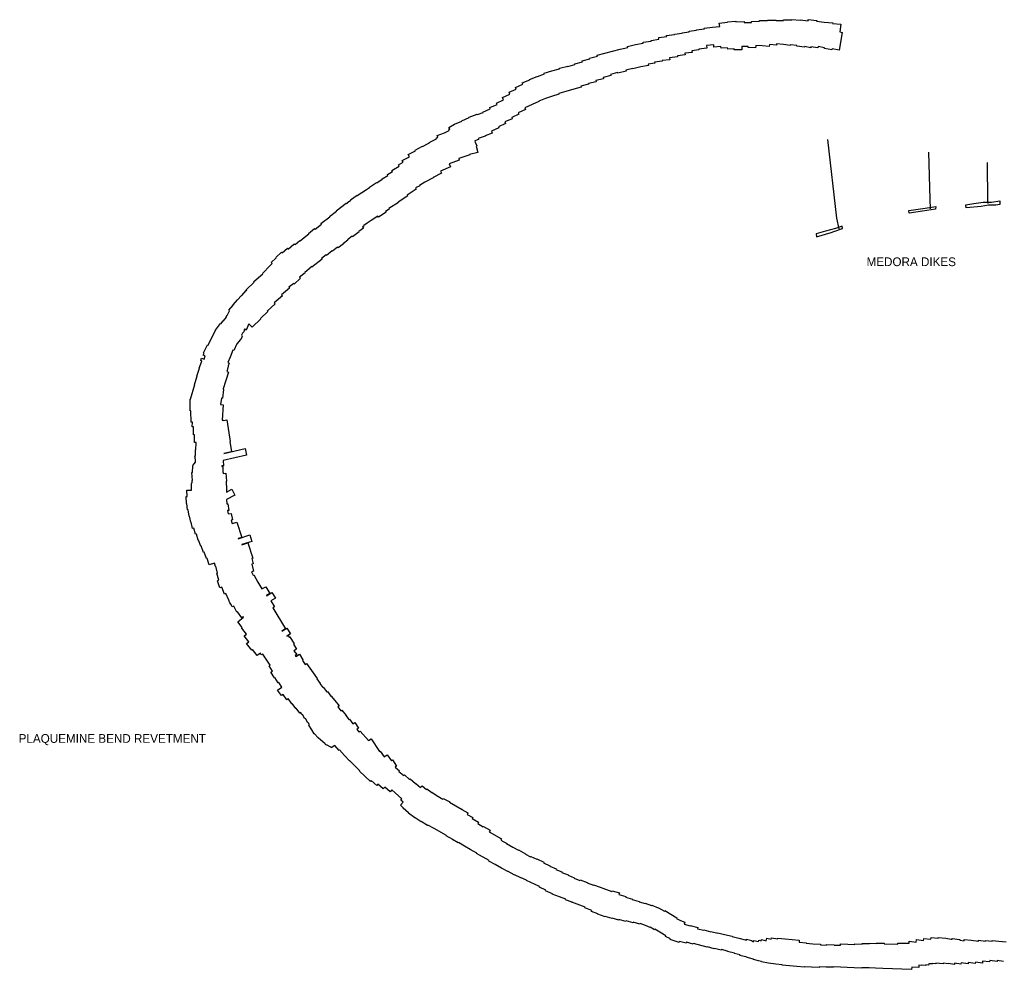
# Model space of a CAD drawing. Extents: x 2650582 to 3923188, y 277893 to 989177.
# Drawn here: x 3308830 to 3326824, y 645331 to 662763 of the extents above; entities that cross this region are included whole.
import ezdxf

# ---------------------------------------------------------------- set-up
doc = ezdxf.new("R2010")
doc.units = 0
doc.layers.add('Level 3', color=7, linetype='Continuous')

msp = doc.modelspace()

# ---------------------------------------------------------------- linework, layer by layer
at = {"layer": 'Level 3'}
for points in [[(3321674, 662633), (3321666, 662698), (3321815, 662714), (3321815, 662722), (3321968, 662731), (3321969, 662723), (3322123, 662725), (3322123, 662710), (3322259, 662710), (3322259, 662730), (3322406, 662731), (3322406, 662748)], [(3322406, 662748), (3322552, 662748), (3322552, 662751), (3322708, 662752), (3322708, 662748), (3322845, 662749), (3322845, 662759), (3322997, 662757), (3322997, 662763), (3323149, 662755), (3323149, 662757), (3323295, 662742), (3323297, 662762), (3323453, 662746), (3323452, 662732), (3323591, 662716), (3323591, 662718), (3323747, 662702), (3323746, 662694), (3323894, 662678), (3323879, 662536)], [(3320272, 662332), (3320270, 662347), (3320417, 662369), (3320416, 662380), (3320560, 662401), (3320556, 662434), (3320701, 662450), (3320698, 662470), (3320845, 662487), (3320843, 662497), (3320987, 662515), (3320986, 662522), (3321114, 662537), (3321113, 662553), (3321246, 662567), (3321246, 662574), (3321393, 662591), (3321391, 662604), (3321539, 662623), (3321674, 662633)], [(3323879, 662536), (3323921, 662528), (3323863, 662201), (3323735, 662224), (3323732, 662206), (3323594, 662230), (3323597, 662246), (3323478, 662267), (3323474, 662242), (3323346, 662265), (3323343, 662246), (3323228, 662266), (3323227, 662258), (3323088, 662275), (3323089, 662286), (3322970, 662300), (3322969, 662290), (3322845, 662305), (3322845, 662304), (3322716, 662316), (3322714, 662295), (3322585, 662306), (3322581, 662270), (3322452, 662281), (3322452, 662280), (3322335, 662290), (3322333, 662246), (3322194, 662251), (3322194, 662266), (3322082, 662266), (3322082, 662206), (3321942, 662206), (3321942, 662227), (3321821, 662222), (3321820, 662245), (3321699, 662236), (3321697, 662266), (3321567, 662257), (3321564, 662302)], [(3317589, 661206), (3317578, 661232), (3317710, 661289), (3317690, 661335), (3317824, 661395), (3317809, 661428), (3317941, 661487), (3317928, 661518), (3318061, 661576), (3318050, 661602), (3318189, 661660), (3318186, 661666), (3318328, 661720), (3318329, 661718), (3318459, 661769), (3318455, 661780), (3318594, 661823), (3318594, 661821), (3318735, 661862), (3318733, 661869), (3318885, 661909), (3318886, 661904), (3319016, 661939), (3319014, 661952), (3319156, 661988), (3319151, 662007), (3319289, 662042), (3319287, 662052), (3319432, 662089), (3319427, 662107), (3319566, 662145), (3319566, 662145), (3319849, 662217), (3319849, 662220), (3319988, 662253), (3319985, 662270), (3320127, 662303), (3320272, 662332)], [(3321564, 662302), (3321433, 662286), (3321439, 662238), (3321291, 662221), (3321293, 662205), (3321163, 662190), (3321167, 662160), (3321036, 662145), (3321040, 662115), (3320897, 662097), (3320899, 662080), (3320753, 662063), (3320757, 662025), (3320618, 662010), (3320620, 662001), (3320479, 661981), (3320482, 661964), (3320359, 661946)], [(3320359, 661946), (3320365, 661920), (3320226, 661893), (3320081, 661859), (3320080, 661865), (3319953, 661835), (3319957, 661818), (3319803, 661780), (3319801, 661790), (3319673, 661757), (3319678, 661738), (3319537, 661700), (3319543, 661678), (3319400, 661642), (3319405, 661623), (3319264, 661589), (3319266, 661580), (3319125, 661544), (3319130, 661523), (3318997, 661487), (3318998, 661485), (3318852, 661446), (3318722, 661408), (3318725, 661396), (3318587, 661353), (3318586, 661354), (3318479, 661312), (3318479, 661313), (3318354, 661265), (3318357, 661258), (3318233, 661206), (3318234, 661203), (3318097, 661143), (3318111, 661113), (3317978, 661053), (3317991, 661024), (3317858, 660964), (3317868, 660941), (3317734, 660884), (3317747, 660856)], [(3316810, 660841), (3316809, 660844), (3316943, 660901), (3316941, 660905), (3317080, 660963), (3317078, 660969), (3317226, 661025), (3317228, 661020), (3317333, 661058), (3317330, 661065), (3317464, 661124), (3317454, 661147), (3317589, 661206)], [(3315851, 660179), (3315982, 660246), (3315961, 660286), (3316091, 660354), (3316084, 660366), (3316221, 660437), (3316222, 660436), (3316324, 660488), (3316324, 660489), (3316348, 660501), (3316346, 660506), (3316478, 660575), (3316470, 660589), (3316504, 660606), (3316493, 660637), (3316623, 660682), (3316708, 660726), (3316702, 660742), (3316722, 660749), (3316703, 660785), (3316810, 660841)], [(3317747, 660856), (3317614, 660797), (3317624, 660774), (3317489, 660714), (3317502, 660679), (3317372, 660632), (3317374, 660626), (3317244, 660578), (3317250, 660565), (3317180, 660536)], [(3323863, 658925), (3323820, 659119), (3323655, 660565)], [(3317180, 660536), (3317185, 660515), (3317220, 660447), (3317205, 660439), (3317235, 660325)], [(3317235, 660325), (3317086, 660286), (3317088, 660281), (3316885, 660211), (3316894, 660182), (3316708, 660118), (3316734, 660058), (3316551, 659978), (3316570, 659943), (3316417, 659864), (3316420, 659859), (3316265, 659782), (3316267, 659779), (3316169, 659719), (3316173, 659710), (3316104, 659679), (3316093, 659672), (3316107, 659650), (3315941, 659542), (3315951, 659527), (3315774, 659415), (3315781, 659403), (3315601, 659296), (3315610, 659282), (3315544, 659243), (3315554, 659227), (3315412, 659139), (3315400, 659158), (3315298, 659087), (3315296, 659089), (3315294, 659087)], [(3325543, 659291), (3325534, 659470), (3325510, 660330)], [(3314646, 659244), (3314640, 659253), (3314822, 659392), (3314826, 659387), (3314846, 659401), (3314843, 659405), (3314906, 659446), (3314900, 659456), (3315021, 659538), (3315022, 659537), (3315191, 659646), (3315192, 659644), (3315251, 659680), (3315248, 659685), (3315380, 659770), (3315382, 659768), (3315483, 659837), (3315481, 659841), (3315588, 659902), (3315578, 659919), (3315669, 659972), (3315658, 659992), (3315691, 660010), (3315690, 660010), (3315794, 660070), (3315781, 660096), (3315868, 660144), (3315851, 660179)], [(3326583, 660137), (3326589, 659426), (3326591, 659388)], [(3325153, 659212), (3325143, 659261), (3325441, 659301), (3325639, 659334)], [(3325639, 659334), (3325635, 659282), (3325394, 659247), (3325153, 659212)], [(3326198, 659309), (3326191, 659364), (3326334, 659385), (3326507, 659412), (3326658, 659413), (3326812, 659439)], [(3326812, 659439), (3326816, 659372), (3326738, 659359), (3326606, 659356), (3326473, 659334), (3326198, 659309)], [(3312990, 657788), (3312997, 657796), (3312988, 657806), (3313136, 657943), (3313125, 657958), (3313292, 658096), (3313287, 658100), (3313426, 658250), (3313463, 658289), (3313447, 658306), (3313539, 658391), (3313531, 658399), (3313633, 658495), (3313646, 658482), (3313745, 658570), (3313759, 658555), (3313761, 658556), (3313858, 658644), (3313865, 658637), (3313875, 658645), (3313884, 658633), (3313970, 658710), (3313976, 658703), (3314016, 658733), (3314022, 658738), (3314020, 658741), (3314135, 658833), (3314130, 658839), (3314241, 658930), (3314252, 658917), (3314366, 659008), (3314357, 659021), (3314521, 659144), (3314516, 659151), (3314646, 659244)], [(3315294, 659087), (3315295, 659086), (3315206, 659026), (3315207, 659025), (3315147, 658981), (3315149, 658979), (3315121, 658959), (3315140, 658934), (3315055, 658872), (3315059, 658867), (3314940, 658775), (3314931, 658786), (3314847, 658723), (3314852, 658717), (3314769, 658652), (3314773, 658647), (3314672, 658573), (3314662, 658587), (3314569, 658515), (3314564, 658521), (3314460, 658436), (3314452, 658445), (3314370, 658379), (3314381, 658364), (3314193, 658219), (3314183, 658232), (3314172, 658224), (3314177, 658218), (3314062, 658122), (3314067, 658117), (3313967, 658035), (3313984, 658016), (3313869, 657910), (3313860, 657920), (3313772, 657849), (3313784, 657834), (3313636, 657711), (3313652, 657692), (3313500, 657567), (3313518, 657546), (3313372, 657412), (3313382, 657403), (3313247, 657276), (3313253, 657269), (3313097, 657117), (3313035, 657180)], [(3323918, 658972), (3323801, 658930), (3323617, 658879), (3323445, 658828), (3323450, 658776)], [(3323450, 658776), (3323717, 658855), (3323769, 658872), (3323928, 658928), (3323918, 658972)], [(3312623, 657302), (3312619, 657306), (3312640, 657331), (3312638, 657332), (3312678, 657419), (3312668, 657428), (3312748, 657524), (3312745, 657527), (3312825, 657622), (3312829, 657618), (3312899, 657702), (3312905, 657697), (3312985, 657792), (3312990, 657788)], [(3311970, 653537), (3311949, 653652), (3311939, 653651), (3311923, 653767), (3311911, 653766), (3311899, 653884), (3311893, 653883), (3311885, 654007), (3311904, 654008), (3311900, 654125), (3311985, 654128), (3311985, 654143), (3311983, 654241), (3311998, 654270), (3311998, 654305), (3312001, 654305), (3311992, 654452), (3312002, 654453), (3312007, 654572), (3312011, 654572), (3312008, 654576), (3312055, 654637), (3312055, 654699), (3312053, 654701), (3312052, 654740), (3312045, 654743), (3312059, 654776), (3312058, 654864), (3312065, 654864), (3312067, 654999), (3312039, 654999), (3312038, 655139), (3312017, 655139), (3312021, 655289), (3311998, 655291), (3312003, 655373), (3311977, 655376), (3311970, 655582), (3311956, 655582), (3311959, 655799), (3311967, 655799), (3312044, 656066), (3312039, 656067), (3312086, 656218), (3312081, 656220), (3312129, 656364), (3312126, 656366), (3312175, 656495), (3312152, 656506), (3312168, 656548), (3312213, 656529), (3312235, 656591), (3312200, 656605), (3312214, 656640), (3312206, 656644), (3312275, 656793), (3312288, 656787), (3312366, 656952), (3312368, 656952), (3312426, 657056), (3312422, 657060), (3312517, 657183), (3312519, 657181), (3312566, 657234), (3312568, 657232), (3312623, 657302)], [(3313035, 657180), (3312985, 657063), (3312960, 657088), (3312947, 657068), (3312948, 657065), (3312941, 657032), (3312918, 657010), (3312899, 656974), (3312911, 656948), (3312887, 656890), (3312884, 656891), (3312817, 656814), (3312760, 656688), (3312742, 656696), (3312692, 656568), (3312690, 656569), (3312651, 656468), (3312674, 656458), (3312654, 656406), (3312659, 656404), (3312637, 656321), (3312639, 656321), (3312633, 656305), (3312664, 656294), (3312567, 655985), (3312565, 655973), (3312571, 655972), (3312550, 655814), (3312531, 655817), (3312517, 655700), (3312567, 655695), (3312543, 655411), (3312572, 655410), (3312571, 655405), (3312630, 655414), (3312695, 655021), (3312689, 655020), (3312716, 654832), (3312579, 654800), (3312579, 654798), (3312965, 654890), (3312991, 654768), (3312567, 654670), (3312570, 654572), (3312558, 654571), (3312558, 654570), (3312542, 654570), (3312540, 654559), (3312558, 654559), (3312556, 654452), (3312565, 654452), (3312565, 654435), (3312611, 654439), (3312623, 654289), (3312619, 654288), (3312626, 654146), (3312624, 654146), (3312626, 654092), (3312723, 654144), (3312781, 654034), (3312627, 653953), (3312629, 653873), (3312652, 653876)], [(3312652, 653876), (3312669, 653753), (3312644, 653750), (3312655, 653689), (3312709, 653700), (3312735, 653579), (3312711, 653574), (3312721, 653535), (3312727, 653515), (3312753, 653523), (3312754, 653521), (3312817, 653541), (3312905, 653260), (3312837, 653238), (3312837, 653235), (3313051, 653304)], [(3312153, 653099), (3312114, 653210), (3312104, 653208), (3312072, 653320), (3312054, 653316), (3312026, 653428), (3312000, 653423), (3311975, 653538), (3311970, 653537)], [(3313051, 653304), (3313088, 653186), (3312907, 653127), (3312907, 653125), (3313017, 653161), (3313109, 652878), (3313091, 652872), (3313116, 652777), (3313088, 652768), (3313120, 652639), (3313082, 652627), (3313115, 652569), (3313126, 652575), (3313198, 652437), (3313199, 652438), (3313275, 652314), (3313345, 652354), (3313419, 652227), (3313359, 652190), (3313359, 652189), (3313458, 652250), (3313525, 652145), (3313439, 652092), (3313508, 651986), (3313474, 651965), (3313710, 651581), (3313639, 651538), (3313640, 651537), (3313735, 651596), (3313801, 651490), (3313733, 651448), (3313733, 651447), (3313755, 651460), (3313774, 651429), (3313788, 651436), (3313867, 651307), (3313853, 651301), (3313912, 651206), (3313863, 651176), (3313913, 651112), (3313887, 651092), (3313898, 651074), (3313963, 651115), (3314028, 651010), (3314017, 651003), (3314066, 650928), (3314094, 650947), (3314155, 650857)], [(3313585, 650596), (3313576, 650590), (3313513, 650688), (3313505, 650683), (3313439, 650788), (3313469, 650807), (3313410, 650905), (3313424, 650914), (3313400, 650953), (3313342, 651045), (3313340, 651043), (3313293, 651119), (3313264, 651102), (3313247, 651133), (3313191, 651089), (3313103, 651200), (3313089, 651190), (3312993, 651309), (3313036, 651343), (3312952, 651453), (3312991, 651484), (3312906, 651595), (3312915, 651603), (3312831, 651712), (3312938, 651796), (3312933, 651806), (3312904, 651784), (3312826, 651891), (3312812, 651885), (3312757, 651997), (3312731, 651984), (3312711, 652026), (3312688, 652057), (3312670, 652105), (3312615, 652228), (3312590, 652218), (3312539, 652343), (3312506, 652331), (3312458, 652462), (3312486, 652473), (3312450, 652600), (3312460, 652603), (3312428, 652730), (3312421, 652728), (3312412, 652769), (3312405, 652789), (3312310, 652757), (3312270, 652874), (3312259, 652871), (3312218, 652989), (3312202, 652984), (3312161, 653102), (3312153, 653099)], [(3314155, 650857), (3314156, 650858), (3314214, 650771), (3314218, 650774), (3314289, 650672), (3314280, 650666), (3314342, 650580), (3314336, 650576), (3314390, 650502), (3314400, 650510), (3314466, 650423), (3314477, 650431), (3314542, 650344), (3314548, 650348), (3314612, 650263), (3314615, 650265), (3314691, 650167), (3314667, 650149), (3314725, 650075), (3314743, 650089), (3314820, 649991), (3314816, 649989), (3314873, 649914), (3314882, 649921), (3314946, 649835)], [(3314613, 649438), (3314547, 649397), (3314538, 649411), (3314458, 649452), (3314450, 649448), (3314437, 649471), (3314307, 649579), (3314242, 649652), (3314234, 649654), (3314191, 649728), (3314189, 649726), (3314136, 649814), (3314147, 649821), (3314126, 649859), (3314118, 649854), (3314076, 649935), (3314064, 649929), (3314021, 650008), (3314010, 650001), (3313987, 650043), (3313972, 650032), (3313901, 650125), (3313896, 650121), (3313831, 650209), (3313827, 650206), (3313759, 650301), (3313731, 650281), (3313665, 650377), (3313633, 650356), (3313564, 650458), (3313642, 650511), (3313585, 650596)], [(3314946, 649835), (3314982, 649859), (3315050, 649755), (3315017, 649734), (3315058, 649687), (3315075, 649703), (3315232, 649530), (3315278, 649560), (3315432, 649328), (3315446, 649338), (3315517, 649231), (3315576, 649271), (3315651, 649161), (3315671, 649174), (3315746, 649060), (3315719, 649042), (3315797, 648974), (3315790, 648965), (3315879, 648887), (3315890, 648899), (3315985, 648814), (3315998, 648829), (3316094, 648741), (3316098, 648745), (3316185, 648667), (3316214, 648700), (3316293, 648633), (3316303, 648647), (3316391, 648579), (3316393, 648582), (3316473, 648527), (3316473, 648529), (3316595, 648455), (3316603, 648469), (3316720, 648404), (3316718, 648400)], [(3316438, 647918), (3316436, 647915), (3316319, 647980), (3316313, 647972), (3316197, 648043), (3316194, 648039), (3316084, 648114), (3316081, 648111), (3315963, 648201), (3315964, 648203), (3315864, 648289), (3315869, 648295), (3315816, 648345), (3315866, 648400), (3315825, 648438), (3315842, 648458), (3315658, 648625), (3315627, 648589), (3315528, 648677), (3315500, 648646), (3315402, 648731), (3315383, 648708), (3315282, 648796), (3315269, 648782), (3315066, 648969), (3315070, 648974), (3314973, 649070), (3314975, 649072), (3314885, 649164), (3314879, 649158), (3314792, 649256), (3314789, 649254), (3314701, 649358), (3314691, 649349), (3314613, 649438)], [(3316718, 648400), (3316947, 648268), (3316944, 648264), (3317053, 648202), (3317038, 648176), (3317143, 648118), (3317132, 648099), (3317247, 648032), (3317234, 648009), (3317337, 647950), (3317338, 647952), (3317461, 647883), (3317443, 647853), (3317671, 647727), (3317658, 647703), (3317766, 647642), (3317765, 647639), (3317881, 647575), (3317880, 647573), (3317980, 647517), (3317984, 647524), (3318114, 647454), (3318108, 647444), (3318205, 647398), (3318208, 647405), (3318319, 647354), (3318320, 647358), (3318447, 647297), (3318443, 647288), (3318560, 647232), (3318557, 647228), (3318671, 647175), (3318666, 647166), (3318780, 647119), (3318776, 647110), (3318893, 647064), (3318891, 647058), (3319006, 647014), (3319002, 647002), (3319110, 646965), (3319113, 646974), (3319245, 646926), (3319243, 646920), (3319356, 646878)], [(3319208, 646473), (3318964, 646562), (3318966, 646566), (3318845, 646608), (3318848, 646618), (3318735, 646661), (3318734, 646660), (3318602, 646714), (3318604, 646719), (3318481, 646770), (3318486, 646784), (3318365, 646840), (3318370, 646851), (3318131, 646965), (3318132, 646966), (3318029, 647014), (3318028, 647012), (3317912, 647068), (3317907, 647070), (3317906, 647068), (3317791, 647130), (3317788, 647125), (3317671, 647190), (3317671, 647188), (3317552, 647253), (3317552, 647254), (3317437, 647318), (3317443, 647328), (3317214, 647455), (3317219, 647464), (3317098, 647532), (3317096, 647530), (3316990, 647590), (3316992, 647595), (3316880, 647660), (3316878, 647656), (3316774, 647714), (3316775, 647715), (3316658, 647781), (3316662, 647789), (3316438, 647918)], [(3319356, 646878), (3319359, 646884), (3319478, 646840), (3319478, 646841), (3319698, 646762), (3319701, 646772), (3319833, 646734), (3319825, 646705), (3319950, 646668), (3319947, 646658), (3320073, 646622), (3320071, 646615), (3320197, 646578), (3320195, 646572), (3320304, 646541), (3320307, 646548), (3320425, 646505), (3320428, 646512), (3320546, 646459), (3320549, 646463), (3320660, 646401), (3320665, 646409), (3320777, 646345), (3320775, 646342), (3320887, 646278), (3320879, 646264), (3320952, 646225), (3321033, 646195), (3321022, 646160), (3321133, 646132), (3321134, 646135), (3321270, 646101), (3321264, 646078), (3321380, 646048), (3321382, 646055), (3321511, 646023), (3321511, 646027), (3321637, 645993), (3321640, 646002), (3321764, 645971), (3321765, 645974), (3321901, 645940), (3321900, 645937), (3322028, 645904), (3322027, 645901), (3322163, 645866), (3322167, 645884)], [(3322046, 645586), (3322049, 645595), (3321941, 645622), (3321943, 645629), (3321818, 645662), (3321819, 645667), (3321704, 645696), (3321701, 645686), (3321576, 645716), (3321574, 645710), (3321449, 645743), (3321447, 645738), (3321192, 645803), (3321190, 645796), (3321064, 645828), (3321060, 645811), (3320935, 645843), (3320928, 645823), (3320766, 645882), (3320769, 645889), (3320679, 645937), (3320686, 645948), (3320575, 646011), (3320577, 646014), (3320485, 646067), (3320479, 646057), (3320398, 646103), (3320397, 646101), (3320312, 646139), (3320310, 646135), (3320212, 646171), (3320209, 646160), (3320086, 646195), (3320084, 646187), (3319958, 646223), (3319954, 646208), (3319826, 646245), (3319824, 646236), (3319702, 646272), (3319701, 646267), (3319574, 646304), (3319571, 646296), (3319439, 646344), (3319441, 646349), (3319320, 646393), (3319328, 646412), (3319202, 646458), (3319208, 646473)], [(3322167, 645884), (3322266, 645861), (3322263, 645847), (3322294, 645839), (3322300, 645863), (3322386, 645842), (3322393, 645866), (3322434, 645855), (3322439, 645877), (3322529, 645855), (3322540, 645901), (3322620, 645883), (3322624, 645909), (3322741, 645891), (3322742, 645901), (3322873, 645889), (3322873, 645892), (3323006, 645878), (3323006, 645880), (3323133, 645866), (3323129, 645829), (3323260, 645821), (3323260, 645809), (3323384, 645802), (3323384, 645800), (3323525, 645791), (3323524, 645780), (3323631, 645776), (3323631, 645787), (3323773, 645783), (3323773, 645778), (3323891, 645774), (3323892, 645800), (3324025, 645793), (3324025, 645796), (3324156, 645790), (3324156, 645800), (3324287, 645796), (3324288, 645806), (3324420, 645803), (3324420, 645809), (3324546, 645806), (3324547, 645814), (3324691, 645810), (3324691, 645801), (3324942, 645792), (3324943, 645815), (3325147, 645809), (3325151, 645846)], [(3325151, 645846), (3325280, 645833), (3325285, 645877), (3325414, 645863), (3325418, 645897), (3325547, 645883), (3325551, 645918), (3325680, 645905), (3325681, 645916), (3325820, 645901), (3325820, 645901), (3325920, 645885), (3325920, 645885), (3325939, 645883), (3325941, 645896), (3326080, 645882), (3326078, 645868)], [(3326078, 645868), (3326157, 645857), (3326160, 645881), (3326287, 645865), (3326287, 645869), (3326419, 645849), (3326422, 645869), (3326550, 645851), (3326551, 645863), (3326670, 645850), (3326672, 645864), (3326795, 645849), (3326796, 645851), (3326929, 645835)], [(3325195, 645331), (3324666, 645347), (3324666, 645349), (3324534, 645353), (3324534, 645355), (3324414, 645358), (3324414, 645357), (3324282, 645360), (3324281, 645354), (3324139, 645359), (3324139, 645361), (3323762, 645375), (3323761, 645370), (3323628, 645374), (3323628, 645371), (3323499, 645376), (3323498, 645364), (3323360, 645373), (3323360, 645371), (3323232, 645378), (3323232, 645372), (3323091, 645381), (3323091, 645385), (3322956, 645399), (3322955, 645396), (3322822, 645410), (3322822, 645415), (3322701, 645426), (3322701, 645428), (3322568, 645448), (3322567, 645444), (3322442, 645472), (3322443, 645475), (3322388, 645488), (3322387, 645487), (3322292, 645514), (3322294, 645519), (3322175, 645548), (3322176, 645553), (3322046, 645586)], [(3325772, 645445), (3325771, 645430), (3325642, 645444), (3325640, 645432), (3325583, 645438), (3325583, 645433), (3325510, 645434), (3325507, 645409), (3325455, 645414), (3325454, 645405), (3325376, 645408), (3325376, 645402), (3325329, 645407), (3325327, 645364), (3325197, 645370), (3325195, 645331)], [(3326879, 645477), (3326764, 645491), (3326763, 645478), (3326628, 645495), (3326625, 645468), (3326498, 645482), (3326493, 645448), (3326366, 645466), (3326360, 645437), (3326233, 645456), (3326231, 645435), (3326102, 645452), (3326098, 645426), (3325984, 645442), (3325981, 645421), (3325868, 645437), (3325867, 645430), (3325772, 645445)]]:
    msp.add_lwpolyline(points, dxfattribs=at)

# ---------------------------------------------------------------- texts
for s, p in [('MEDORA DIKES', (3324368, 658238)), ('PLAQUEMINE BEND REVETMENT', (3308812, 649489))]:
    msp.add_text(s, height=160, dxfattribs=at).set_placement(p)

doc.saveas('drawing.dxf')
